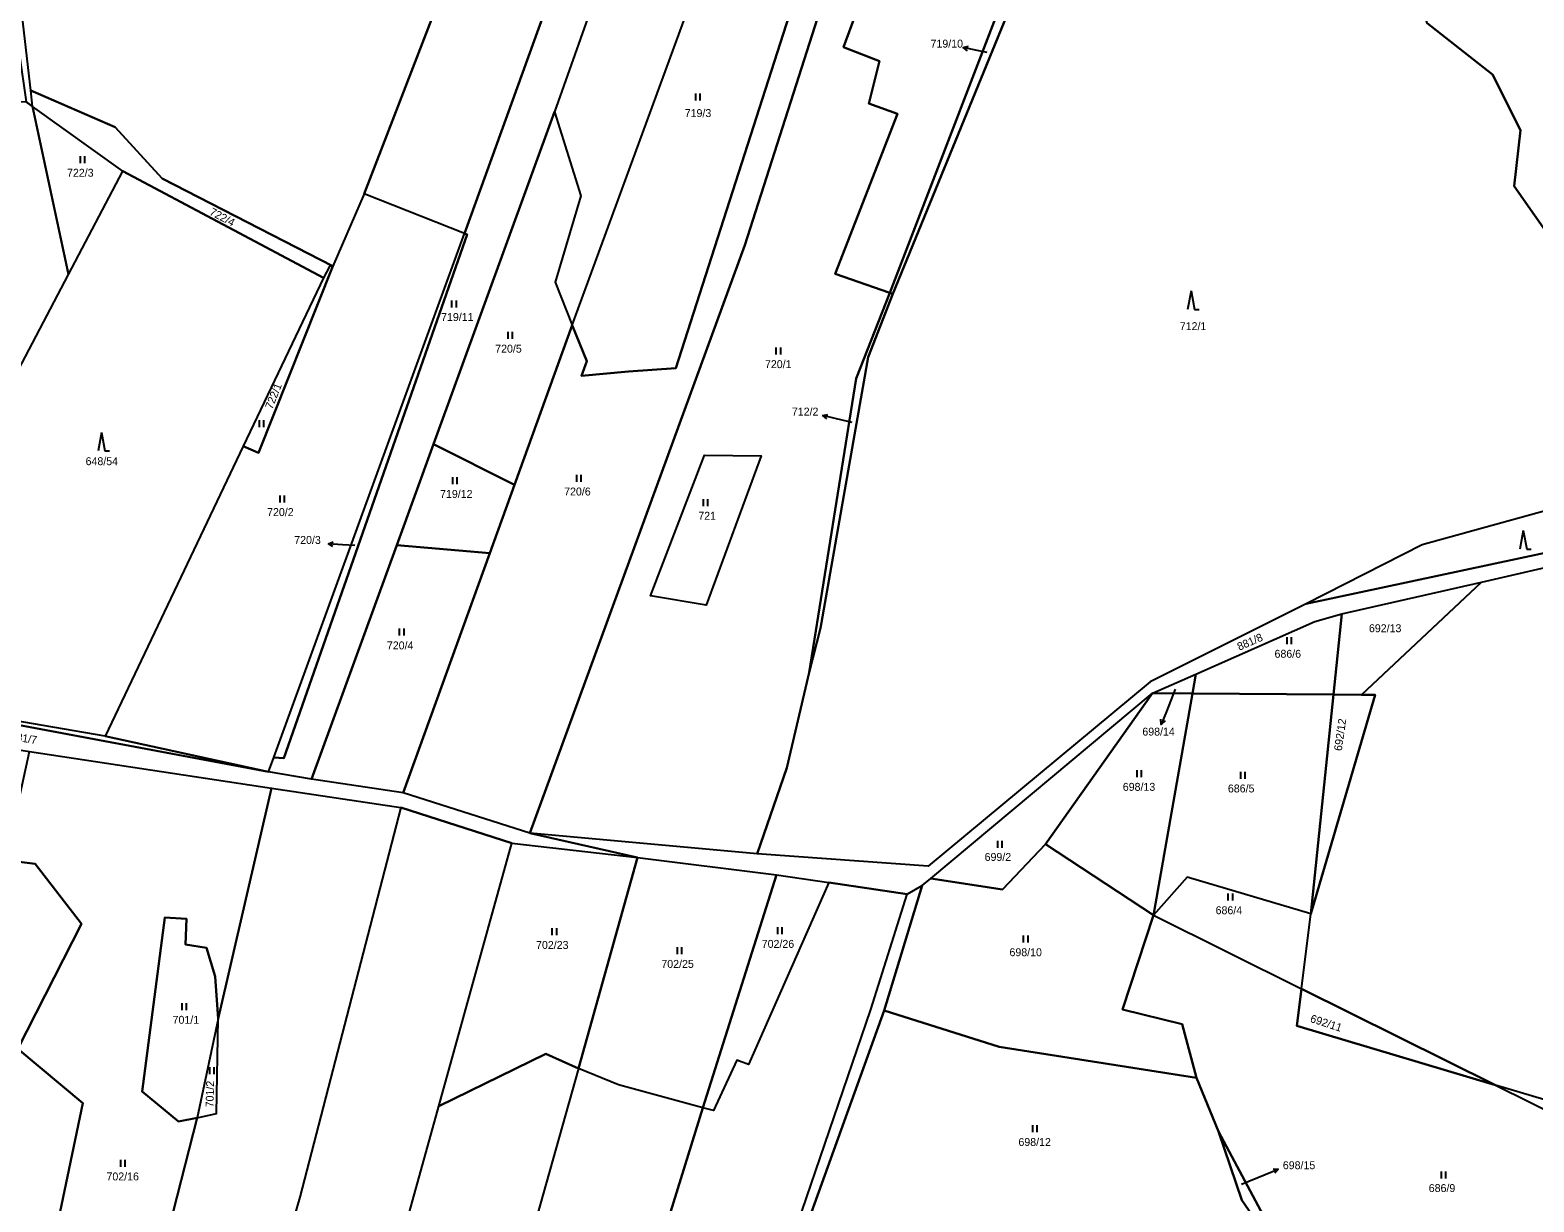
# Model space of a CAD drawing. Extents: x -654083 to -650132, y -1099819 to -1096699.
# Drawn here: x -652845.6 to -652523.2, y -1099068.9 to -1098817.7 of the extents above; entities that cross this region are included whole.
import ezdxf

# ---------------------------------------------------------------- set-up
doc = ezdxf.new("R2010")
doc.units = 0
for name, color, linetype in [('Obvody jako plochy', 7, 'Continuous'), ('Parcelní čísla', 7, 'Continuous'), ('Prvky pro prodl_ par_ č_', 7, 'Continuous'), ('Značky kultur', 7, 'Continuous')]:
    doc.layers.add(name, color=color, linetype=linetype)

msp = doc.modelspace()

# ---------------------------------------------------------------- linework, layer by layer
at = {"layer": 'Obvody jako plochy'}
for points in [[(-652773.99, -1098852.83), (-652780.71, -1098868.34), (-652817.3, -1098849.53), (-652827.37, -1098838.48), (-652845.44, -1098830.64), (-652853.14, -1098764.41), (-652852.73, -1098762.77), (-652837.25, -1098745.76), (-652821.07, -1098736.01), (-652804.17, -1098736.91), (-652800.2, -1098738.06), (-652739.31, -1098758.15), (-652740.97, -1098767.26)], [(-652452.51, -1098893.28), (-652489.4, -1098908.18), (-652496.8, -1098910.33), (-652509.63, -1098896.65), (-652518.74, -1098863.59), (-652527.47, -1098851.14), (-652526.09, -1098839.17), (-652532.1, -1098827.19), (-652546.11, -1098816.23), (-652548.42, -1098807.57), (-652553.68, -1098802.81), (-652545.83, -1098787.84), (-652534.7, -1098766.31), (-652521.52, -1098758.36)], [(-652845.44, -1098830.64), (-652853.14, -1098764.41), (-652854.51, -1098769.98), (-652854.03, -1098780.82), (-652846.44, -1098833.08), (-652845.04, -1098834.08)], [(-652733.15, -1098835.25), (-652759.1, -1098906.44), (-652767, -1098928.11), (-652785.3, -1098978.31), (-652794.48, -1098976.74), (-652793.36, -1098973.66), (-652791.23, -1098973.77), (-652751.87, -1098861.52), (-652752.47, -1098861.3), (-652718.34, -1098766.78), (-652709.73, -1098769.07)], [(-652740.97, -1098767.26), (-652730.78, -1098765.53), (-652718.34, -1098766.78), (-652752.47, -1098861.3), (-652773.99, -1098852.83)], [(-652729.36, -1098880.96), (-652691.15, -1098776.69), (-652696.54, -1098773.4), (-652709.73, -1098769.07), (-652733.15, -1098835.25), (-652727.55, -1098853.24), (-652733.06, -1098871.71)], [(-652682.96, -1098779.32), (-652672.59, -1098782.5), (-652707.19, -1098890.16), (-652717.32, -1098890.92), (-652727.35, -1098891.85), (-652726.27, -1098888.69), (-652729.36, -1098880.96), (-652691.15, -1098776.69)], [(-652672.59, -1098782.5), (-652668.17, -1098783.86), (-652666.93, -1098784.24), (-652692.34, -1098863.82), (-652738.43, -1098989.85), (-652765.64, -1098981.22), (-652747.05, -1098929.85), (-652741.75, -1098915.2), (-652729.36, -1098880.96), (-652726.27, -1098888.69), (-652727.35, -1098891.85), (-652717.32, -1098890.92), (-652707.19, -1098890.16)], [(-652671.21, -1098821.36), (-652663.52, -1098824.33), (-652665.78, -1098833.44), (-652659.65, -1098835.63), (-652672.98, -1098869.94), (-652661.27, -1098874), (-652668.5, -1098892.39), (-652678.55, -1098955.41), (-652683.38, -1098975.88), (-652689.7, -1098994.29), (-652738.43, -1098989.85), (-652692.34, -1098863.82), (-652666.93, -1098784.24), (-652658.49, -1098786.85)], [(-652638.52, -1098793.03), (-652631.03, -1098795.35), (-652661.27, -1098874), (-652672.98, -1098869.94), (-652659.65, -1098835.63), (-652665.78, -1098833.44), (-652663.52, -1098824.33), (-652671.21, -1098821.36), (-652658.49, -1098786.85)], [(-652625.87, -1098789.16), (-652660.61, -1098874.25), (-652661.27, -1098874), (-652631.03, -1098795.35)], [(-652845.44, -1098830.64), (-652827.37, -1098838.48), (-652817.3, -1098849.53), (-652780.71, -1098868.34), (-652781.43, -1098868.37), (-652782.69, -1098870.79), (-652825.7, -1098847.93), (-652845.04, -1098834.08)], [(-652884.39, -1098959.63), (-652837.37, -1098870.13), (-652845.04, -1098834.08), (-652846.44, -1098833.08), (-652880.48, -1098834.85), (-652929.53, -1098958.94), (-652918.13, -1098956.4)], [(-652825.7, -1098847.93), (-652845.04, -1098834.08), (-652837.37, -1098870.13)], [(-652733.15, -1098835.25), (-652727.55, -1098853.24), (-652733.06, -1098871.71), (-652729.36, -1098880.96), (-652741.75, -1098915.2), (-652759.1, -1098906.44)], [(-652825.7, -1098847.93), (-652782.69, -1098870.79), (-652799.89, -1098906.91), (-652829.49, -1098969.08), (-652884.39, -1098959.63), (-652837.37, -1098870.13)], [(-652780.71, -1098868.34), (-652796.6, -1098908.34), (-652799.89, -1098906.91), (-652829.49, -1098969.08), (-652794.48, -1098976.74), (-652793.36, -1098973.66), (-652752.47, -1098861.3), (-652773.99, -1098852.83)], [(-652752.47, -1098861.3), (-652751.87, -1098861.52), (-652791.23, -1098973.77), (-652793.36, -1098973.66)], [(-652781.43, -1098868.37), (-652782.69, -1098870.79), (-652799.89, -1098906.91), (-652796.6, -1098908.34), (-652780.71, -1098868.34)], [(-652665.91, -1098887.81), (-652676.15, -1098945.95), (-652678.55, -1098955.41), (-652668.5, -1098892.39), (-652661.27, -1098874), (-652660.61, -1098874.25)], [(-652829.49, -1098969.08), (-652884.39, -1098959.63), (-652918.13, -1098956.4), (-652929.53, -1098958.94), (-652942.08, -1098959.73), (-652975.23, -1098949.5), (-652974.5, -1098947.53), (-652988.86, -1098937.84), (-652990.08, -1098937.02), (-653008.3, -1098904.33), (-653010.8, -1098907.8), (-652994.21, -1098938.87), (-652977.03, -1098952.43), (-652948.28, -1098960.67), (-652927.86, -1098961.97), (-652910.13, -1098958.2), (-652884.15, -1098960.83), (-652859.4, -1098964.6), (-652794.48, -1098976.74)], [(-652759.1, -1098906.44), (-652741.75, -1098915.2), (-652747.05, -1098929.85), (-652767, -1098928.11)], [(-652570.16, -1098944.51), (-652564.38, -1098942.88), (-652534.46, -1098936.04), (-652506.83, -1098929.73), (-652499.93, -1098927.38), (-652491.19, -1098915.88), (-652487.1, -1098910.26), (-652489.4, -1098908.18), (-652493.83, -1098913.33), (-652503.82, -1098924.95), (-652510.07, -1098927.5), (-652572.05, -1098940.7), (-652605.45, -1098957.43), (-652653.08, -1098996.95), (-652689.7, -1098994.29), (-652738.43, -1098989.85), (-652715.35, -1098995.1), (-652685.59, -1098998.84), (-652674.38, -1099000.48), (-652657.55, -1099002.94), (-652654.36, -1099001.13), (-652652.47, -1098999.61), (-652604.94, -1098959.84), (-652595.68, -1098955.76)], [(-652700.69, -1098940.97), (-652712.59, -1098938.97), (-652700.99, -1098908.85), (-652688.9, -1098908.95)], [(-652688.9, -1098908.95), (-652700.69, -1098940.97), (-652712.59, -1098938.97), (-652700.99, -1098908.85)], [(-652547.18, -1098928.05), (-652572.05, -1098940.7), (-652510.07, -1098927.5), (-652503.82, -1098924.95), (-652493.83, -1098913.33)], [(-652747.05, -1098929.85), (-652765.64, -1098981.22), (-652785.3, -1098978.31), (-652767, -1098928.11)], [(-652468.54, -1099018.95), (-652485.76, -1099057.5), (-652531.41, -1099043.9), (-652573.02, -1099023.24), (-652571.06, -1099007.16), (-652557.25, -1098960.25), (-652560.16, -1098960.22), (-652534.46, -1098936.04), (-652506.83, -1098929.73), (-652411.98, -1098946.66), (-652440.79, -1098966.74), (-652456.94, -1098995.42)], [(-652534.46, -1098936.04), (-652560.16, -1098960.22), (-652566.18, -1098960.17), (-652564.38, -1098942.88)], [(-652564.38, -1098942.88), (-652566.18, -1098960.17), (-652596.41, -1098959.91), (-652595.68, -1098955.76), (-652570.16, -1098944.51)], [(-652766.11, -1098984.41), (-652742.33, -1098992.01), (-652715.35, -1098995.1), (-652738.43, -1098989.85), (-652765.64, -1098981.22), (-652785.3, -1098978.31), (-652794.48, -1098976.74), (-652859.4, -1098964.6), (-652884.15, -1098960.83), (-652910.13, -1098958.2), (-652927.86, -1098961.97), (-652948.28, -1098960.67), (-652977.03, -1098952.43), (-652959.14, -1098961.76), (-652936.01, -1098965.85), (-652910.58, -1098962.59), (-652874.38, -1098967.87), (-652845.75, -1098972.4), (-652793.87, -1098980.22)], [(-652604.94, -1098959.84), (-652595.68, -1098955.76), (-652596.41, -1098959.91)], [(-652604.94, -1098959.84), (-652627.9, -1098992.21), (-652637.1, -1099001.95), (-652652.47, -1098999.61)], [(-652596.41, -1098959.91), (-652604.75, -1099007.48), (-652627.9, -1098992.21), (-652604.94, -1098959.84)], [(-652596.41, -1098959.91), (-652566.18, -1098960.17), (-652571.06, -1099007.16), (-652597.53, -1098999.35), (-652604.75, -1099007.48)], [(-652557.25, -1098960.25), (-652571.06, -1099007.16), (-652566.18, -1098960.17), (-652560.16, -1098960.22)], [(-652827.88, -1099121.75), (-652845.42, -1099186.87), (-652846.55, -1099186.57), (-652846.09, -1099184.77), (-652829.65, -1099121.29), (-652848.38, -1099115.11), (-652834.28, -1099047.75), (-652848.21, -1099036.14), (-652834.57, -1099009.35), (-652844.48, -1098996.43), (-652850.81, -1098995.64), (-652845.75, -1098972.4), (-652793.87, -1098980.22), (-652805.29, -1099029.68), (-652805.89, -1099020.61), (-652807.74, -1099014.47), (-652812.3, -1099013.77), (-652812.07, -1099008.28), (-652816.71, -1099007.93), (-652821.53, -1099045.3), (-652813.78, -1099051.69), (-652809.81, -1099050.94)], [(-652766.11, -1098984.41), (-652787.77, -1099067.92), (-652814.91, -1099161.23), (-652823.91, -1099188.64), (-652832.92, -1099186.32), (-652832.94, -1099189.44), (-652845.42, -1099186.87), (-652827.88, -1099121.75), (-652809.81, -1099050.94), (-652805.61, -1099050.02), (-652805.29, -1099029.68), (-652793.87, -1098980.22)], [(-652764.28, -1099071.04), (-652757.98, -1099048.43), (-652742.33, -1098992.01), (-652766.11, -1098984.41), (-652787.77, -1099067.92), (-652814.91, -1099161.23), (-652823.91, -1099188.64), (-652800.14, -1099194.77), (-652786.69, -1099140.42), (-652783.74, -1099140.87)], [(-652715.35, -1098995.1), (-652728.02, -1099040.33), (-652735, -1099037.22), (-652757.98, -1099048.43), (-652742.33, -1098992.01)], [(-652604.75, -1099007.48), (-652611.41, -1099027.66), (-652598.64, -1099030.86), (-652595.51, -1099042.32), (-652637.87, -1099035.68), (-652662.49, -1099027.9), (-652654.36, -1099001.13), (-652652.47, -1098999.61), (-652637.1, -1099001.95), (-652627.9, -1098992.21)], [(-652834.28, -1099047.75), (-652848.38, -1099115.11), (-652829.65, -1099121.29), (-652846.09, -1099184.77), (-652892.51, -1099172.5), (-652863.61, -1099053.36), (-652850.81, -1098995.64), (-652844.48, -1098996.43), (-652834.57, -1099009.35), (-652848.21, -1099036.14)], [(-652685.59, -1098998.84), (-652701.37, -1099048.77), (-652719.46, -1099043.83), (-652728.02, -1099040.33), (-652715.35, -1098995.1)], [(-652685.59, -1098998.84), (-652674.38, -1099000.48), (-652691.55, -1099039.51), (-652694.1, -1099038.56), (-652699.11, -1099049.36), (-652701.37, -1099048.77)], [(-652597.53, -1098999.35), (-652604.75, -1099007.48), (-652573.02, -1099023.24), (-652571.06, -1099007.16)], [(-652674.38, -1099000.48), (-652691.55, -1099039.51), (-652694.1, -1099038.56), (-652699.11, -1099049.36), (-652701.37, -1099048.77), (-652749.79, -1099205.17), (-652737.14, -1099208.72), (-652726.38, -1099214.16), (-652709.36, -1099162.16), (-652691.37, -1099102.65), (-652680.17, -1099070.99), (-652665.33, -1099027.7), (-652657.55, -1099002.94)], [(-652688.96, -1099102.81), (-652706.9, -1099162.49), (-652724.09, -1099215.32), (-652724.87, -1099217.71), (-652727.16, -1099216.54), (-652726.38, -1099214.16), (-652709.36, -1099162.16), (-652691.37, -1099102.65), (-652680.17, -1099070.99), (-652665.33, -1099027.7), (-652657.55, -1099002.94), (-652654.36, -1099001.13), (-652662.49, -1099027.9), (-652678.11, -1099071.15)], [(-652805.29, -1099029.68), (-652809.81, -1099050.94), (-652813.78, -1099051.69), (-652821.53, -1099045.3), (-652816.71, -1099007.93), (-652812.07, -1099008.28), (-652812.3, -1099013.77), (-652807.74, -1099014.47), (-652805.89, -1099020.61)], [(-652486.72, -1099066.1), (-652504.77, -1099092.04), (-652509.84, -1099106.19), (-652505.66, -1099110.73), (-652507.62, -1099115.29), (-652573.21, -1099086.81), (-652590.85, -1099053.87), (-652595.51, -1099042.32), (-652598.64, -1099030.86), (-652611.41, -1099027.66), (-652604.75, -1099007.48), (-652573.02, -1099023.24), (-652574, -1099031.22), (-652531.41, -1099043.9)], [(-652482.57, -1099058.59), (-652479.79, -1099058.92), (-652468.54, -1099018.95), (-652485.76, -1099057.5), (-652531.41, -1099043.9), (-652486.72, -1099066.1)], [(-652573.02, -1099023.24), (-652531.41, -1099043.9), (-652574, -1099031.22)], [(-652595.51, -1099042.32), (-652590.85, -1099053.87), (-652585.81, -1099068.6), (-652573.21, -1099086.81), (-652572.78, -1099092.57), (-652678.11, -1099071.15), (-652662.49, -1099027.9), (-652637.87, -1099035.68)], [(-652805.29, -1099029.68), (-652809.81, -1099050.94), (-652805.61, -1099050.02)], [(-652757.98, -1099048.43), (-652735, -1099037.22), (-652728.02, -1099040.33), (-652773, -1099200), (-652784.32, -1099198), (-652799.38, -1099194.97), (-652783.74, -1099140.87), (-652760.87, -1099144.21), (-652764.28, -1099071.04)], [(-652701.37, -1099048.77), (-652719.46, -1099043.83), (-652728.02, -1099040.33), (-652773, -1099200), (-652753.83, -1099203.59), (-652749.79, -1099205.17)], [(-652590.85, -1099053.87), (-652573.21, -1099086.81), (-652585.81, -1099068.6)]]:
    msp.add_lwpolyline(points, close=True, dxfattribs=at)
msp.add_lwpolyline([(-652546.11, -1098816.23), (-652532.1, -1098827.19), (-652526.09, -1098839.17), (-652527.47, -1098851.14), (-652518.74, -1098863.59), (-652509.63, -1098896.65), (-652496.8, -1098910.33), (-652489.4, -1098908.18), (-652493.83, -1098913.33), (-652547.18, -1098928.05), (-652572.05, -1098940.7), (-652605.45, -1098957.43), (-652653.08, -1098996.95), (-652689.7, -1098994.29), (-652683.38, -1098975.88), (-652678.55, -1098955.41), (-652676.15, -1098945.95), (-652665.91, -1098887.81), (-652660.61, -1098874.25), (-652625.87, -1098789.16)], dxfattribs=at)
at = {"layer": 'Prvky pro prodl_ par_ č_'}
for p, q in [((-652642.59, -1098822.04), (-652645.53, -1098821.45)), ((-652640.42, -1098822.48), (-652642.59, -1098822.04)), ((-652672.73, -1098901.03), (-652675.65, -1098900.34)), ((-652669.37, -1098901.83), (-652672.73, -1098901.03)), ((-652778.65, -1098928.03), (-652781.64, -1098927.86)), ((-652775.94, -1098928.19), (-652778.65, -1098928.03)), ((-652600.09, -1098959.04), (-652602, -1098963.77)), ((-652602, -1098963.77), (-652603.13, -1098966.55)), ((-652585.87, -1099065.11), (-652580.81, -1099063.06)), ((-652580.81, -1099063.06), (-652578.03, -1099061.93))]:
    msp.add_line(p, q, dxfattribs=at)
for points in [[(-652644.65, -1098822.14), (-652645.53, -1098821.45), (-652644.45, -1098821.15)], [(-652674.79, -1098901.05), (-652675.65, -1098900.34), (-652674.56, -1098900.08)], [(-652780.68, -1098928.41), (-652781.64, -1098927.86), (-652780.62, -1098927.42)], [(-652602.29, -1098965.81), (-652603.13, -1098966.55), (-652603.21, -1098965.44)], [(-652579.14, -1099061.84), (-652578.03, -1099061.93), (-652578.77, -1099062.77)]]:
    msp.add_lwpolyline(points, dxfattribs=at)
at = {"layer": 'Značky kultur'}
for p, q in [((-652702.97, -1098831.26), (-652702.97, -1098832.76)), ((-652701.95, -1098832.76), (-652701.95, -1098831.26)), ((-652834.89, -1098844.7), (-652834.89, -1098846.2)), ((-652833.86, -1098846.2), (-652833.86, -1098844.7)), ((-652596.7, -1098873.63), (-652597.44, -1098877.63)), ((-652596.7, -1098873.63), (-652595.97, -1098877.63)), ((-652755.22, -1098875.64), (-652755.22, -1098877.14)), ((-652754.2, -1098877.14), (-652754.2, -1098875.64)), ((-652595.97, -1098877.63), (-652594.97, -1098877.63)), ((-652743.18, -1098882.42), (-652743.18, -1098883.92)), ((-652742.16, -1098883.92), (-652742.16, -1098882.42)), ((-652685.69, -1098885.74), (-652685.69, -1098887.24)), ((-652684.67, -1098887.24), (-652684.67, -1098885.74)), ((-652796.48, -1098901.34), (-652796.48, -1098902.84)), ((-652795.45, -1098902.84), (-652795.45, -1098901.34)), ((-652830.29, -1098903.94), (-652831.03, -1098907.94)), ((-652830.29, -1098903.94), (-652829.56, -1098907.94)), ((-652829.56, -1098907.94), (-652828.56, -1098907.94)), ((-652728.44, -1098913.04), (-652728.44, -1098914.54)), ((-652727.42, -1098914.54), (-652727.42, -1098913.04)), ((-652755.07, -1098913.56), (-652755.07, -1098915.06)), ((-652754.05, -1098915.06), (-652754.05, -1098913.56)), ((-652792.05, -1098917.46), (-652792.05, -1098918.96)), ((-652791.03, -1098918.96), (-652791.03, -1098917.46)), ((-652701.31, -1098918.25), (-652701.31, -1098919.75)), ((-652700.29, -1098919.75), (-652700.29, -1098918.25)), ((-652525.49, -1098925), (-652526.22, -1098929)), ((-652525.49, -1098925), (-652524.76, -1098929)), ((-652524.76, -1098929), (-652523.76, -1098929)), ((-652766.44, -1098946.03), (-652766.44, -1098947.53)), ((-652765.42, -1098947.53), (-652765.42, -1098946.03)), ((-652576.18, -1098947.83), (-652576.18, -1098949.33)), ((-652575.16, -1098949.33), (-652575.16, -1098947.83)), ((-652608.33, -1098976.36), (-652608.33, -1098977.86)), ((-652607.31, -1098977.86), (-652607.31, -1098976.36)), ((-652586.14, -1098976.72), (-652586.14, -1098978.22)), ((-652585.11, -1098978.22), (-652585.11, -1098976.72)), ((-652638.22, -1098991.52), (-652638.22, -1098993.02)), ((-652637.2, -1098993.02), (-652637.2, -1098991.52)), ((-652588.8, -1099002.82), (-652588.8, -1099004.32)), ((-652587.78, -1099004.32), (-652587.78, -1099002.82)), ((-652733.71, -1099010.27), (-652733.71, -1099011.77)), ((-652732.69, -1099011.77), (-652732.69, -1099010.27)), ((-652685.4, -1099010.03), (-652685.4, -1099011.53)), ((-652684.38, -1099011.53), (-652684.38, -1099010.03)), ((-652632.67, -1099011.82), (-652632.67, -1099013.32)), ((-652631.65, -1099013.32), (-652631.65, -1099011.82)), ((-652706.88, -1099014.32), (-652706.88, -1099015.82)), ((-652705.85, -1099015.82), (-652705.85, -1099014.32)), ((-652813.06, -1099026.31), (-652813.06, -1099027.81)), ((-652812.04, -1099027.81), (-652812.04, -1099026.31)), ((-652807.14, -1099040.08), (-652807.14, -1099041.58)), ((-652806.11, -1099041.58), (-652806.11, -1099040.08)), ((-652630.71, -1099052.52), (-652630.71, -1099054.02)), ((-652629.69, -1099054.02), (-652629.69, -1099052.52)), ((-652826.24, -1099059.9), (-652826.24, -1099061.4)), ((-652825.21, -1099061.4), (-652825.21, -1099059.9)), ((-652543.12, -1099062.4), (-652543.12, -1099063.9)), ((-652542.09, -1099063.9), (-652542.09, -1099062.4))]:
    msp.add_line(p, q, dxfattribs=at)

# ---------------------------------------------------------------- texts
at = {"layer": 'Parcelní čísla'}
for s, height, rotation, p in [('719/10', 0.1, 68.526, (-652640.42, -1098822.48)), ('722/4', 1.7, 331.983, (-652807.29, -1098857.19)), ('722/1', 1.7, 68.148, (-652793.7, -1098899.1)), ('712/2', 0.1, 79.416, (-652669.37, -1098901.83)), ('720/3', 0.1, 70.974, (-652775.94, -1098928.19)), ('881/8', 1.7, 23.499, (-652586.36, -1098950.77)), ('692/12', 1.7, 81.954, (-652564.4, -1098972.33)), ('881/7', 1.7, 350.991, (-652849.87, -1098969.9)), ('692/11', 1.7, 341.865, (-652571.3, -1099030.32)), ('701/2', 1.7, 88.767, (-652806.27, -1099048.68)), ('698/15', 0.1, 295.884, (-652585.87, -1099065.11))]:
    msp.add_text(s, height=height, rotation=rotation, dxfattribs=at).set_placement(p)
for s, height, p in [('719/3', 1.7, (-652705.25, -1098836.34)), ('722/3', 1.7, (-652837.67, -1098849.13)), ('719/11', 1.7, (-652757.48, -1098880.07)), ('712/1', 1.7, (-652599.12, -1098882.03)), ('720/5', 1.7, (-652745.88, -1098886.85)), ('720/1', 1.7, (-652688.05, -1098890.17)), ('648/54', 1.7, (-652833.69, -1098910.98)), ('719/12', 1.7, (-652757.7, -1098918)), ('720/6', 1.7, (-652731.1, -1098917.48)), ('720/2', 1.7, (-652794.78, -1098921.89)), ('721', 1.7, (-652702.34, -1098922.68)), ('692/13', 1.7, (-652558.57, -1098946.79)), ('720/4', 1.7, (-652769.1, -1098950.47)), ('686/6', 1.7, (-652578.81, -1098952.27)), ('698/14', 0.1, (-652600.09, -1098959.04)), ('698/13', 1.7, (-652611.34, -1098980.8)), ('686/5', 1.7, (-652588.81, -1098981.15)), ('699/2', 1.7, (-652640.96, -1098995.83)), ('686/4', 1.7, (-652591.44, -1099007.26)), ('702/23', 1.7, (-652737.12, -1099014.7)), ('702/26', 1.7, (-652688.74, -1099014.47)), ('698/10', 1.7, (-652635.63, -1099016.26)), ('702/25', 1.7, (-652710.26, -1099018.76)), ('701/1', 1.7, (-652815.04, -1099030.75)), ('698/12', 1.7, (-652633.71, -1099056.95)), ('702/16', 1.7, (-652829.21, -1099064.33)), ('686/9', 1.7, (-652545.75, -1099066.83))]:
    msp.add_text(s, height=height, dxfattribs=at).set_placement(p)
at = {"layer": 'Prvky pro prodl_ par_ č_'}
for s, p in [('719/10', (-652652.55, -1098821.45)), ('712/2', (-652682.28, -1098900.34)), ('720/3', (-652788.96, -1098927.86)), ('698/14', (-652607.15, -1098968.96)), ('698/15', (-652577.03, -1099061.93))]:
    msp.add_text(s, height=1.7, dxfattribs=at).set_placement(p)

doc.saveas('drawing.dxf')
